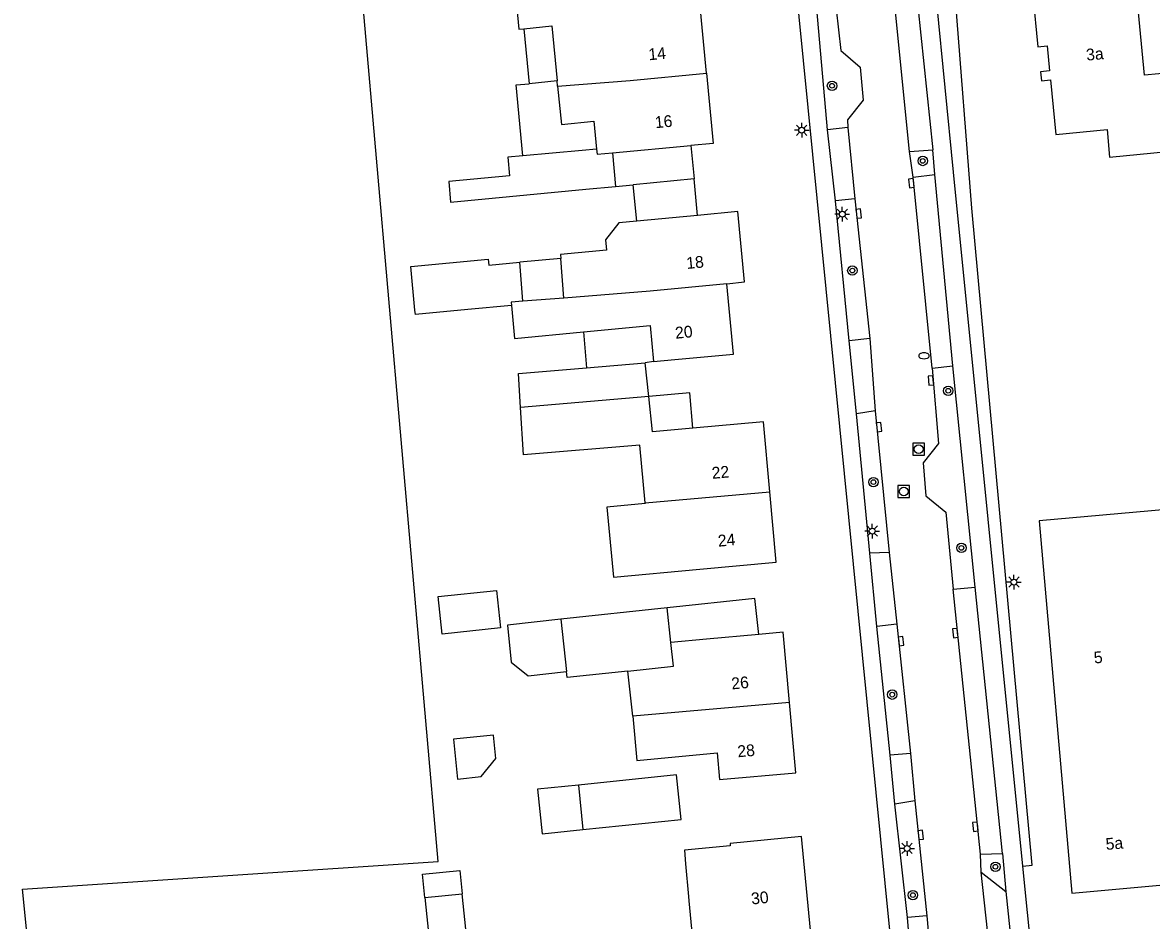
# Model space of a CAD drawing. Extents: x 140000 to 143000, y 403500 to 406000.
# Drawn here: x 140453.4 to 140549.5, y 404278.1 to 404354.5 of the extents above; entities that cross this region are included whole.
import ezdxf

# ---------------------------------------------------------------- set-up
doc = ezdxf.new("R2010")
doc.units = 0
for name, color, linetype in [('gg-afsc-erfafscheiding', 7, 'Continuous'), ('gg-anno-huisnummerreeks BGT', 7, 'Continuous'), ('gg-bbg-bijgebouw', 7, 'Continuous'), ('gg-bbg-gedigitaliseerde bijgebouw', 7, 'Continuous'), ('gg-bbg-hoofdgebouw', 7, 'Continuous'), ('gg-bbg-luifel en loopbrug', 7, 'Continuous'), ('gg-bbg-overig bouwwerk', 7, 'Continuous'), ('gg-bbg-tussenscheiding', 7, 'Continuous'), ('gg-knt-verharding', 7, 'Continuous'), ('gg-knt-verharding nz', 7, 'Continuous'), ('gt-symb-boom', 7, 'Continuous'), ('gt-symb-brandkraan', 7, 'Continuous'), ('gt-symb-kolk', 7, 'Continuous'), ('gt-symb-lichtmast', 7, 'Continuous'), ('gt-symb-rioolschacht', 7, 'Continuous')]:
    doc.layers.add(name, color=color, linetype=linetype)

# ---------------------------------------------------------------- blocks, each defined once
blk = doc.blocks.new('gt0-KOLK')
at = {"layer": 'gt-symb-kolk'}
blk.add_lwpolyline([(0, 0), (0.375, 0), (0.375, 0.4), (-0.375, 0.4), (-0.375, 0), (0, 0)], dxfattribs=at)
blk = doc.blocks.new('gt0-LMAST')
at = {"layer": 'gt-symb-lichtmast'}
for p, q in [((-0.182, 0.173), (-0.447, 0.438)), ((-0.005, 0.246), (-0.005, 0.621)), ((0.172, 0.173), (0.437, 0.438)), ((-0.255, -0.004), (-0.63, -0.004)), ((-0.182, -0.181), (-0.447, -0.446)), ((-0.005, -0.254), (-0.005, -0.629)), ((0.437, -0.446), (0.172, -0.181)), ((0.245, -0.004), (0.62, -0.004))]:
    blk.add_line(p, q, dxfattribs=at)
blk.add_circle((-0.005, -0.004), 0.25, dxfattribs=at)
blk = doc.blocks.new('gt0-BOOM')
at = {"layer": 'gt-symb-boom'}
for radius in [0.4, 0.2]:
    blk.add_circle((0, 0), radius, dxfattribs=at)
blk = doc.blocks.new('gt0-RS')
at = {"layer": 'gt-symb-rioolschacht'}
blk.add_lwpolyline([(-0.5, -0.5), (0.5, -0.5), (0.5, 0.5), (-0.5, 0.5)], close=True, dxfattribs=at)
blk.add_circle((0, 0), 0.375, dxfattribs=at)
blk = doc.blocks.new('gt0-BR')
at = {"layer": 'gt-symb-brandkraan'}
for centre, radius, start, end in [((-0.244, 0), 0.206, 107.56694, 252.43307), ((0.599, -2.664), 3, 106.89205, 107.56694), ((0, -0.691), 0.938, 73.10799, 106.89205), ((-0.599, -2.664), 3, 72.43309, 73.10799), ((0.244, 0), 0.206, 287.56695, 72.43309), ((0.599, 2.664), 3, 252.43307, 253.10797), ((0, 0.691), 0.938, 253.10797, 286.89206), ((-0.599, 2.664), 3, 286.89206, 287.56695)]:
    blk.add_arc(centre, radius, start, end, dxfattribs=at)

msp = doc.modelspace()

# ---------------------------------------------------------------- linework, layer by layer
at = {"layer": 'gg-afsc-erfafscheiding'}
for points in [[(140453.819, 404276.806), (140453.424, 404280.754), (140488.777, 404283.083), (140478.299, 404402.787), (140503.285, 404405.143), (140512.874, 404406.111)], [(140538.538, 404282.69), (140539.31, 404282.783), (140534.197, 404338.666), (140532.79, 404356.452)]]:
    msp.add_lwpolyline(points, dxfattribs=at)
at = {"layer": 'gg-bbg-bijgebouw'}
for p, q in [((140503.61, 404343.381), (140503.882, 404340.52)), ((140495.997, 404330.747), (140495.73, 404334.065)), ((140501.407, 404325.101), (140506.39, 404325.516)), ((140506.694, 404322.653), (140506.39, 404325.516)), ((140508.266, 404304.671), (140499.232, 404303.701)), ((140508.582, 404301.728), (140508.266, 404304.671)), ((140499.232, 404303.701), (140499.708, 404299.262)), ((140509.457, 404286.669), (140509.069, 404290.457))]:
    msp.add_line(p, q, dxfattribs=at)
for points in [[(140495.976, 404343.12), (140494.698, 404343.002), (140494.844, 404341.417), (140489.68, 404340.94), (140489.842, 404339.184), (140501.346, 404340.279), (140503.882, 404340.52)], [(140502.261, 404343.7), (140501.032, 404343.587), (140495.976, 404343.12)], [(140495.007, 404330.399), (140491.316, 404330.05), (140486.845, 404329.627), (140486.809, 404330.006), (140486.459, 404333.701), (140493.044, 404334.324), (140493.092, 404333.816), (140495.73, 404334.065)], [(140495.8, 404321.705), (140495.627, 404324.619), (140501.407, 404325.101)], [(140494.083, 404302.979), (140489.112, 404302.446), (140488.77, 404305.627), (140493.741, 404306.161), (140494.083, 404302.979)], [(140504.931, 404299.293), (140499.771, 404298.739), (140499.708, 404299.262)]]:
    msp.add_lwpolyline(points, dxfattribs=at)
at = {"layer": 'gg-bbg-gedigitaliseerde bijgebouw'}
for p, q in [((140509.069, 404290.457), (140500.713, 404289.601)), ((140500.713, 404289.601), (140501.101, 404285.813)), ((140501.101, 404285.813), (140509.457, 404286.669))]:
    msp.add_line(p, q, dxfattribs=at)
msp.add_lwpolyline([(140492.426, 404290.317), (140493.697, 404291.861), (140493.502, 404293.851), (140490.089, 404293.502), (140490.436, 404290.113), (140492.426, 404290.317)], dxfattribs=at)
at = {"layer": 'gg-bbg-hoofdgebouw'}
for p, q in [((140498.946, 404349.04), (140498.902, 404349.488)), ((140503.61, 404343.381), (140510.29, 404343.997)), ((140510.847, 404338.059), (140505.67, 404337.567)), ((140499.486, 404331.027), (140499.215, 404334.395)), ((140499.486, 404331.027), (140495.997, 404330.747)), ((140505.343, 404295.459), (140504.931, 404299.293))]:
    msp.add_line(p, q, dxfattribs=at)
for points in [[(140495.267, 404357.819), (140495.65, 404353.893), (140496.057, 404353.933)], [(140546.36, 404357.491), (140539.38, 404356.792), (140539.81, 404352.39), (140540.6, 404352.471), (140540.8, 404350.342), (140540.021, 404350.261), (140540.1, 404349.492), (140540.88, 404349.58), (140541.34, 404344.932), (140545.692, 404345.361), (140545.896, 404342.997), (140552.006, 404343.591), (140551.326, 404350.22), (140548.88, 404349.981), (140548.275, 404356.187), (140548.263, 404356.315)], [(140511.621, 404350.145), (140511.05, 404356.13), (140509.282, 404355.962)], [(140496.057, 404353.933), (140498.446, 404354.166), (140498.902, 404349.488)], [(140511.621, 404350.145), (140512.19, 404344.172), (140510.29, 404343.997)], [(140498.946, 404349.04), (140499.264, 404345.788), (140502.03, 404346.058), (140502.261, 404343.7)], [(140513.342, 404332.235), (140514.842, 404332.412), (140514.274, 404338.385), (140510.847, 404338.059)], [(140505.67, 404337.567), (140504.157, 404337.423), (140503.017, 404335.967), (140503.099, 404335.106), (140499.183, 404334.736), (140499.215, 404334.395)], [(140507.1, 404325.618), (140508.93, 404325.791), (140513.91, 404326.262), (140513.342, 404332.235)], [(140495.007, 404330.399), (140495.272, 404327.592), (140501.153, 404328.148)], [(140501.153, 404328.148), (140506.81, 404328.683), (140507.1, 404325.618)], [(140510.452, 404319.958), (140507.013, 404319.646), (140506.694, 404322.653)], [(140506.39, 404313.596), (140505.947, 404318.497), (140496.036, 404317.698), (140495.8, 404321.705)], [(140516.999, 404314.538), (140516.46, 404320.501), (140510.452, 404319.958)], [(140506.39, 404313.596), (140506.395, 404313.544), (140503.145, 404313.25), (140503.685, 404307.289), (140511.056, 404307.974), (140517.54, 404308.562), (140516.999, 404314.538)], [(140552.834, 404303.172), (140554.808, 404305.386), (140554.417, 404309.668), (140554.869, 404309.709), (140555.209, 404309.74), (140555.07, 404311.204), (140556.952, 404311.383), (140556.762, 404313.375), (140554.9, 404313.198), (140554.88, 404313.407), (140539.92, 404312.07), (140542.019, 404288.169), (140542.7, 404280.41), (140555.796, 404281.58), (140555.082, 404289.543)], [(140516.051, 404302.403), (140511.616, 404302.003), (140508.582, 404301.728)], [(140518.665, 404296.618), (140518.13, 404302.59), (140516.051, 404302.403)], [(140505.343, 404295.459), (140505.694, 404291.7), (140512.516, 404292.335), (140512.727, 404290.067), (140519.2, 404290.642), (140518.665, 404296.618)], [(140510.005, 404273.427), (140515.016, 404273.906), (140514.747, 404276.711), (140520.471, 404277.261), (140519.69, 404285.232), (140513.615, 404284.632), (140513.634, 404284.422), (140509.73, 404284.069), (140509.836, 404282.899), (140510.089, 404280.111), (140510.122, 404279.746), (140510.39, 404276.786), (140509.529, 404276.708)]]:
    msp.add_lwpolyline(points, dxfattribs=at)
at = {"layer": 'gg-bbg-luifel en loopbrug'}
for p, q in [((140496.057, 404353.933), (140496.514, 404349.255)), ((140498.902, 404349.488), (140496.514, 404349.255)), ((140510.29, 404343.997), (140510.552, 404341.155)), ((140510.552, 404341.155), (140505.376, 404340.663)), ((140510.847, 404338.059), (140510.552, 404341.155)), ((140503.882, 404340.52), (140505.376, 404340.663)), ((140505.67, 404337.567), (140505.376, 404340.663)), ((140499.215, 404334.395), (140495.73, 404334.065)), ((140501.153, 404328.148), (140501.407, 404325.101)), ((140507.1, 404325.618), (140506.39, 404325.516)), ((140487.658, 404280.035), (140490.825, 404280.354))]:
    msp.add_line(p, q, dxfattribs=at)
for points in [[(140495.976, 404343.12), (140495.419, 404349.148), (140496.514, 404349.255)], [(140510.452, 404319.958), (140510.181, 404322.956), (140506.694, 404322.653)], [(140516.051, 404302.403), (140515.723, 404305.471), (140508.266, 404304.671)], [(140499.232, 404303.701), (140494.677, 404303.212), (140494.985, 404300.062), (140496.451, 404298.881), (140499.708, 404299.262)], [(140500.713, 404289.601), (140497.231, 404289.245), (140497.619, 404285.457), (140501.101, 404285.813)], [(140487.658, 404280.035), (140487.458, 404282.025), (140490.624, 404282.344), (140490.825, 404280.354)]]:
    msp.add_lwpolyline(points, dxfattribs=at)
at = {"layer": 'gg-bbg-overig bouwwerk'}
msp.add_lwpolyline([(140487.658, 404280.035), (140488.043, 404276.207), (140491.211, 404276.526), (140490.825, 404280.354)], dxfattribs=at)
at = {"layer": 'gg-bbg-tussenscheiding'}
for p, q in [((140506.694, 404322.653), (140495.8, 404321.705)), ((140506.39, 404313.596), (140516.999, 404314.538)), ((140518.665, 404296.618), (140505.343, 404295.459))]:
    msp.add_line(p, q, dxfattribs=at)
for points in [[(140498.946, 404349.04), (140505.108, 404349.529), (140511.621, 404350.145)], [(140502.261, 404343.7), (140502.304, 404343.26), (140503.61, 404343.381)], [(140513.342, 404332.235), (140506.823, 404331.618), (140499.486, 404331.027)], [(140495.997, 404330.747), (140494.982, 404330.665), (140495.007, 404330.399)], [(140504.931, 404299.293), (140508.799, 404299.708), (140508.582, 404301.728)]]:
    msp.add_lwpolyline(points, dxfattribs=at)
at = {"layer": 'gg-knt-verharding'}
for p, q in [((140521.902, 404345.34), (140520.857, 404357.221)), ((140529.603, 404355.837), (140530.862, 404343.628)), ((140523.625, 404345.524), (140521.902, 404345.34)), ((140522.58, 404339.281), (140521.902, 404345.34)), ((140528.868, 404343.483), (140530.862, 404343.628)), ((140529.192, 404341.301), (140528.868, 404343.483)), ((140531.04, 404341.534), (140530.862, 404343.628)), ((140529.192, 404341.301), (140531.04, 404341.534)), ((140532.582, 404325.272), (140531.04, 404341.534)), ((140524.224, 404339.474), (140522.58, 404339.281)), ((140523.741, 404327.381), (140522.58, 404339.281)), ((140524.224, 404339.474), (140525.519, 404327.577)), ((140525.519, 404327.577), (140523.741, 404327.381)), ((140524.377, 404321.178), (140523.741, 404327.381)), ((140530.822, 404325.057), (140532.582, 404325.272)), ((140534.476, 404306.43), (140532.582, 404325.272)), ((140525.95, 404321.428), (140524.377, 404321.178)), ((140525.505, 404309.333), (140524.377, 404321.178)), ((140525.95, 404321.428), (140527.166, 404309.367)), ((140527.166, 404309.367), (140525.505, 404309.333)), ((140526.1, 404303.089), (140525.505, 404309.333)), ((140532.594, 404306.262), (140534.476, 404306.43)), ((140536.783, 404283.778), (140534.476, 404306.43)), ((140527.815, 404303.293), (140526.1, 404303.089)), ((140527.234, 404292.132), (140526.1, 404303.089)), ((140527.815, 404303.293), (140528.958, 404292.27)), ((140528.958, 404292.27), (140527.234, 404292.132)), ((140527.627, 404287.974), (140527.234, 404292.132)), ((140529.333, 404288.265), (140527.627, 404287.974)), ((140529.333, 404288.265), (140530.346, 404278.462)), ((140528.712, 404278.324), (140527.627, 404287.974)), ((140534.93, 404283.725), (140536.783, 404283.778)), ((140534.98, 404282.195), (140534.93, 404283.725)), ((140536.783, 404283.778), (140537.09, 404280.549)), ((140534.98, 404282.195), (140537.09, 404280.549)), ((140537.09, 404280.549), (140538.066, 404271.165)), ((140530.346, 404278.462), (140528.712, 404278.324)), ((140529.299, 404271.085), (140528.712, 404278.324))]:
    msp.add_line(p, q, dxfattribs=at)
for points in [[(140514.372, 404406.262), (140514.44, 404405.532), (140527.94, 404269.541), (140532.776, 404220.528)], [(140522.444, 404357.39), (140523.049, 404352.079), (140524.693, 404350.675), (140524.951, 404347.846), (140523.607, 404346.189), (140523.625, 404345.524)], [(140538.538, 404282.69), (140532.614, 404341.72), (140531.2, 404356.134)], [(140530.822, 404325.057), (140531.355, 404318.653), (140530.055, 404316.994), (140530.259, 404314.206), (140531.966, 404312.812), (140532.594, 404306.262)], [(140558.031, 404087.296), (140550.273, 404165.239), (140549.757, 404170.423), (140549.443, 404173.577), (140549.116, 404176.864), (140547.298, 404195.131), (140547.025, 404197.874), (140545.885, 404209.325), (140545.421, 404213.986), (140543.99, 404228.362), (140538.538, 404282.69)]]:
    msp.add_lwpolyline(points, dxfattribs=at)
at = {"layer": 'gg-knt-verharding nz'}
for p, q in [((140528.868, 404343.483), (140527.666, 404355.648)), ((140523.625, 404345.524), (140524.224, 404339.474)), ((140530.822, 404325.057), (140529.192, 404341.301)), ((140525.519, 404327.577), (140525.95, 404321.428)), ((140527.166, 404309.367), (140527.815, 404303.293)), ((140534.93, 404283.725), (140532.594, 404306.262)), ((140528.958, 404292.27), (140529.333, 404288.265)), ((140536.297, 404269.842), (140534.98, 404282.195)), ((140530.346, 404278.462), (140531.02, 404271.351))]:
    msp.add_line(p, q, dxfattribs=at)

# ---------------------------------------------------------------- block references
at = {"layer": 'gt-symb-boom'}
for p in [(140522.291, 404349.08), (140530.008, 404342.685), (140524.019, 404333.367), (140532.177, 404323.136), (140525.817, 404315.366), (140533.298, 404309.777), (140527.409, 404297.289), (140536.198, 404282.652), (140529.168, 404280.236)]:
    msp.add_blockref('gt0-BOOM', p, dxfattribs=at)
at = {"layer": 'gt-symb-brandkraan'}
msp.add_blockref('gt0-BR', (140530.119, 404326.114), dxfattribs=at)
at = {"layer": 'gt-symb-kolk'}
for p, rotation in [((140529.24, 404340.818), 97.0869819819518), ((140524.364, 404338.185), -83.78992443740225), ((140530.907, 404324.03), 94.92045630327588), ((140526.091, 404320.029), -84.24443877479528), ((140532.979, 404302.549), 95.91776668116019), ((140527.968, 404301.818), -84.08223331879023), ((140534.687, 404286.071), 95.91776668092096), ((140529.636, 404285.335), -84.09828780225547)]:
    msp.add_blockref('gt0-KOLK', p, dxfattribs=dict(at, rotation=rotation))
at = {"layer": 'gt-symb-lichtmast'}
for p in [(140519.716, 404345.305), (140523.171, 404338.161), (140525.717, 404311.202), (140537.771, 404306.868), (140528.686, 404284.211)]:
    msp.add_blockref('gt0-LMAST', p, dxfattribs=at)
at = {"layer": 'gt-symb-rioolschacht'}
for p in [(140529.659, 404318.167), (140528.391, 404314.572)]:
    msp.add_blockref('gt0-RS', p, dxfattribs=at)

# ---------------------------------------------------------------- texts
at = {"layer": 'gg-anno-huisnummerreeks BGT'}
for s, rotation, p in [('14', 5.4, (140506.717, 404351.245)), ('3a', 5.4, (140543.956, 404351.21)), ('16', 5.4, (140507.268, 404345.467)), ('18', 5.4, (140509.941, 404333.494)), ('20', 5.4, (140508.988, 404327.56)), ('22', 5.1, (140512.102, 404315.641)), ('24', 5.1, (140512.624, 404309.871)), ('5', 5, (140544.611, 404299.937)), ('26', 5.1, (140513.768, 404297.732)), ('28', 5.1, (140514.285, 404291.958)), ('5a', 5, (140545.614, 404284.073)), ('30', 5.6, (140515.458, 404279.437))]:
    msp.add_text(s, height=1, rotation=rotation, dxfattribs=at).set_placement(p)

doc.saveas('drawing.dxf')
